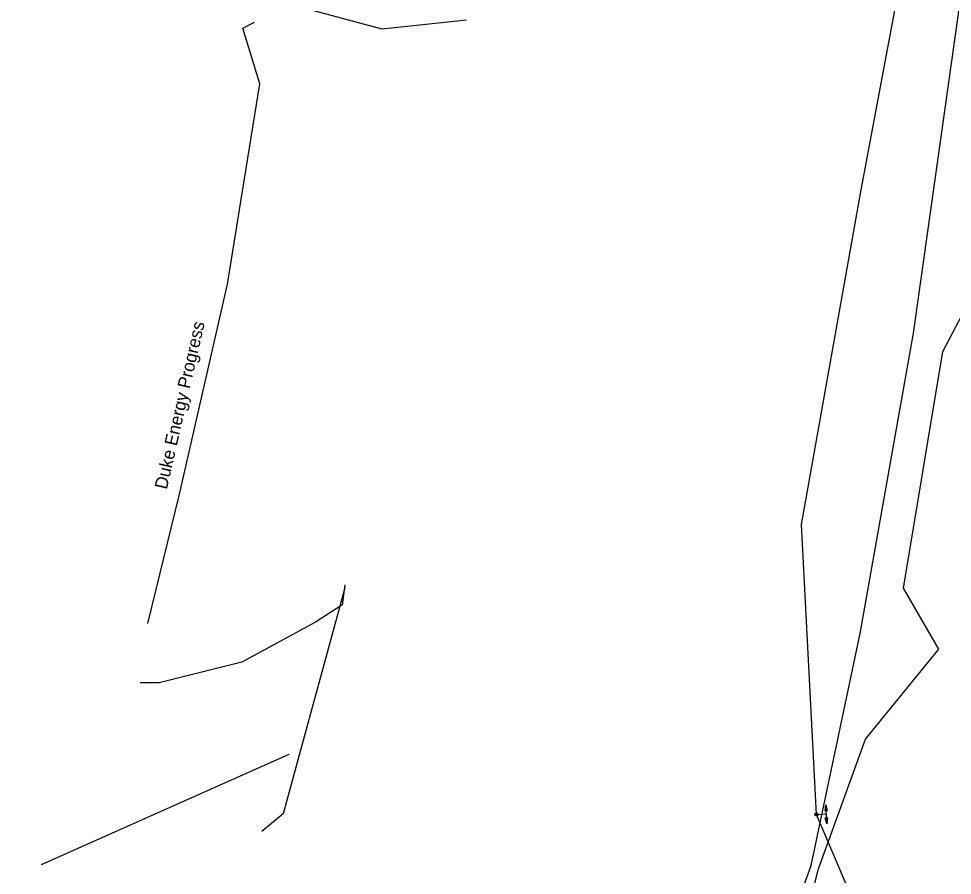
# Model space of a CAD drawing. Extents: x 2070721 to 2083340, y 729290 to 737883.
# Drawn here: x 2082070.1 to 2082363.4, y 735917.7 to 736186.8 of the extents above; entities that cross this region are included whole.
import ezdxf

# ---------------------------------------------------------------- set-up
doc = ezdxf.new("R2010")
doc.units = 0
for name, color, linetype in [('Exist Utilities Power UG Cable SUE LOS B', 7, 'Continuous'), ('Exist Utilities Power UG Cable SUE LOS B Leader', 7, 'Continuous'), ('Exist Utilities Power UG Cable SUE LOS B Text', 7, 'Continuous'), ('Exist Utilities Power UG Cable SUE LOS C', 7, 'Continuous'), ('Exist Utilities Telephone UG Conduit SUE LOS B', 7, 'Continuous'), ('Exist Utilities Water Change of Service SUE CELL', 7, 'Continuous'), ('Exist Utilities Water UG Line SUE LOS B', 7, 'Continuous'), ('Exist Utilities Water UG Line SUE LOS C', 7, 'Continuous')]:
    doc.layers.add(name, color=color, linetype=linetype)

msp = doc.modelspace()

# ---------------------------------------------------------------- linework, layer by layer
at = {"layer": 'Exist Utilities Power UG Cable SUE LOS B'}
msp.add_line((2082172.58, 736009), (2082171.71, 736002.6), dxfattribs=at)
for points in [[(2082210.82, 736186.38), (2082184.27, 736183.56), (2082132.77, 736197.39), (2082078.53, 736213.65), (2082070.12, 736220.15)], [(2082110.71, 735996.86), (2082120.65, 736037.47), (2082135.66, 736103.41), (2082145.82, 736166.3), (2082140.52, 736183.81), (2082144.17, 736185.75)], [(2082172.61, 736008.03), (2082153.24, 735937.02), (2082146.5, 735931.49)]]:
    msp.add_lwpolyline(points, dxfattribs=at)
at = {"layer": 'Exist Utilities Power UG Cable SUE LOS B Leader'}
msp.add_line((2082154.94, 735955.71), (2082077.21, 735921.08), dxfattribs=at)
at = {"layer": 'Exist Utilities Power UG Cable SUE LOS C'}
msp.add_lwpolyline([(2082171.66, 736002.61), (2082163.33, 735997.3), (2082140.18, 735984.73), (2082114.23, 735978.24), (2082108.31, 735978.24)], dxfattribs=at)
at = {"layer": 'Exist Utilities Telephone UG Conduit SUE LOS B'}
for points in [[(2082120.86, 735106.65), (2082121.53, 735109.26), (2082126.82, 735163.37), (2082139.88, 735257.28), (2082147.13, 735321.1), (2082170.45, 735428.84), (2082201.87, 735563.79), (2082232.74, 735685.94), (2082254.12, 735726.65), (2082278.69, 735809.1), (2082319.03, 735920.81), (2082334.41, 735993.71), (2082351.13, 736088.05), (2082365.28, 736188.35), (2082370.12, 736249.49)], [(2082311, 735883.41), (2082314.93, 735894.57), (2082321.33, 735919.82), (2082336.09, 735960.51), (2082359.13, 735988.75), (2082348, 736007.91), (2082360.44, 736082.28), (2082381.79, 736122.83), (2082393.52, 736182.23), (2082374.75, 736205.67), (2082370.42, 736249.5)]]:
    msp.add_lwpolyline(points, dxfattribs=at)
at = {"layer": 'Exist Utilities Water Change of Service SUE CELL'}
for p, q in [((2082323.92, 735933.89), (2082323.62, 735939.84)), ((2082320.68, 735936.86), (2082323.76, 735937.02)), ((2082320.68, 735936.86), (2082320.68, 735936.86)), ((2082323.76, 735937.02), (2082323.92, 735933.89))]:
    msp.add_line(p, q, dxfattribs=at)
for points in [[(2082323.62, 735939.84), (2082324.06, 735937.89), (2082323.7, 735938.29), (2082323.41, 735937.89)], [(2082323.92, 735933.89), (2082323.48, 735935.84), (2082323.84, 735935.43), (2082324.13, 735935.83)]]:
    msp.add_lwpolyline(points, close=True, dxfattribs=at)
msp.add_circle((2082320.68, 735936.86), 0.517, dxfattribs=at)
at = {"layer": 'Exist Utilities Water UG Line SUE LOS B'}
msp.add_lwpolyline([(2082320.68, 735936.86), (2082316.05, 736027.92), (2082334.72, 736133.01), (2082351.23, 736221.26), (2082359.3, 736290.13)], dxfattribs=at)
at = {"layer": 'Exist Utilities Water UG Line SUE LOS C'}
msp.add_lwpolyline([(2082136.84, 735123.04), (2082168.96, 735173.67), (2082194.75, 735239.91), (2082279.19, 735526.38), (2082326.09, 735735.17), (2082347.15, 735840.56), (2082331.47, 735911.49), (2082320.68, 735936.86)], dxfattribs=at)

# ---------------------------------------------------------------- texts
at = {"layer": 'Exist Utilities Power UG Cable SUE LOS B Text'}
msp.add_text('Duke Energy Progress', height=4, rotation=77.1762, dxfattribs=at).set_placement((2082116.65, 736038.77))

doc.saveas('drawing.dxf')
